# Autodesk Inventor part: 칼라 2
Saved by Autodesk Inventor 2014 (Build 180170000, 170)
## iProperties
Created: 2026-04
Part Number: 칼라 2
Material: 강철, 연강
Document SubType Name: Modeling
Designer: dg
Density: 7.86 g/cm^3
Appearance: 강철
Mass: 5.16082 g
Surface Area: 8.86637 cm^2
Volume: 0.656593 cm^3
Author: jhkim
Creation Date: 2026-03-27
Sending System: Autodesk Inventor 2026
Preprocessor: ST-DEVELOPER v20.1
Author: dg
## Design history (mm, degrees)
node "칼라 21"
node "솔리드1"
node "기준1"
